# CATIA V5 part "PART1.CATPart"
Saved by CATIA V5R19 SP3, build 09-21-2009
Part number: PART1
Bounding box of the stored display mesh (mm): x -10.392 to 10.392, y -6.9 to 85.6, z -9 to 9
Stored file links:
  C:\Documents and Settings\Frielingsdorf\Desktop\PART1.CATPart
  P1.CATPart
  X:\CATIA\R19\intel_a\reffiles\standard\MetricThickPitch.txt
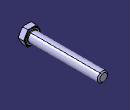
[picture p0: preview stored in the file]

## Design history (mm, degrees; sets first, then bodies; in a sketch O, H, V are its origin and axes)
Body1 "MainBody" (main body), material "Kein"
  Sketch1 on yz-plane, origin (0, 0, 0), H (0, 1, 0), V (0, 0, 1)
    line L1 (0, 8.315) -> (0, 8.9066)
    line L2 (0.6, 8.1967) -> (0.6, 6.6)
    line L3 (1.2, 6) -> (85.6, 6)
    line L4 (85.6, 6) -> (85.6, 0)
    point P3 (85.6, 0)
    line L5 (85.6, 0) -> (0, 0)
    arc A1 centre (0.6, 8.9066) radius 0.6 from (0.5, 8.315) to (0, 8.9066) cw
    arc A2 centre (0.48, 8.1967) radius 0.12 from (0.5, 8.315) to (0.6, 8.1967) cw
    point P8 (0.5, 8.315)
    arc A3 centre (1.2, 6.6) radius 0.6 from (0.6, 6.6) to (1.2, 6) ccw
    line L6 (0, 8.315) -> (0, 0)
    distance L2 L4 = 85
    length L4 = 6
    distance P8 L5 = 8.315
    distance L2 L1 = 0.6
    distance L2 P8 = 0.1
    radius A1 = 0.6
    radius A3 = 0.6
    length L6 = 8.315
    vertical: L1 V, L2 V, L4 V
    horizontal: L3 H, L5 H
    coincidence: P3 H, L6 V
    tangency: A1 L1, A2 L2, A2 A1, A3 L2, A3 L3, L6 A1
  Shaft1: profile Sketch1, axis Y axis, angle 360
  Sketch2 on face of Shaft1 from Sketch1.L6, origin (0, 0, 0), H (1, 0, 0), V (0, 0, 1)
    point P1 (5.1962, -9)
    point P2 (10.3923, 0)
    point P3 (5.1962, 9)
    point P4 (-5.1962, 9)
    point P5 (-10.3923, 0)
    point P6 (-5.1962, -9)
    point P7 (7.7942, -4.5)
    line L1 (5.1962, -9) -> (10.3923, 0)
    line L2 (10.3923, 0) -> (5.1962, 9)
    line L3 (5.1962, 9) -> (-5.1962, 9)
    line L4 (-5.1962, 9) -> (-10.3923, 0)
    line L5 (-10.3923, 0) -> (-5.1962, -9)
    line L6 (-5.1962, -9) -> (5.1962, -9)
    construction line L7 (0, 0) -> (7.7942, -4.5)
    construction circle A1 centre (0, 0) radius 10.3923
    construction arc A2 centre (-10.3923, 0) radius 10.3923 from (-5.1962, 9) to (-5.1962, -9) cw
    construction arc A3 centre (10.3923, 0) radius 10.3923 from (5.1962, 9) to (5.1962, -9) ccw
    construction circle A4 centre (0, 0) radius 9
    reference intersected line E1 through (0, 0) direction (-1, 0) from xy-plane
    distance L4 L1 = 18
    coincidence: A1 P1, A1 P2, A1 P3, A1 P4, A1 P5, A1 P6, A2 O, A3 O
    midpoint: P7 L1
    tangency: A4 L2
    parallelism: L3 E1
  Pad1: profile Sketch2, direction (0, -1, 0), length 6.9
  Sketch3 on xy-plane, origin (0, 0, 0), H (1, 0, 0), V (0, 1, 0)
    line L1 (-10.3923, -6.0962) -> (-10.3923, -6.9)
    line L2 (-10.3923, -6.9) -> (-9, -6.9)
    point P3 (-9, -6.9)
    line L3 (-9, -6.9) -> (-10.3923, -6.0962)
    reference projected line E1 (-10.3923, 0) -> (-10.3923, -6.9) from edge [face of Pad1 from Sketch2.L5 | face of Pad1 from Sketch2.L4]
    reference projected line E2 (-5.1962, -6.9) -> (-10.3923, -6.9) from edge [face of Pad1 from Sketch2.L4 | end face of Pad1]
    angle L3 L2 = 30
    distance P3 V = 9
    coincidence: L1 E1, L2 E2
  Groove1: profile Sketch3, axis Y axis, angle 360
  Chamfer1: length 1.5, angle 45, on edge [face of Shaft1 from Sketch1.L3 | face of Shaft1 from Sketch1.L4]
  Thread1: "M12", diameter 12, depth 30, pitch 1.75, on face of Shaft1 from Sketch1.L3, from face of Shaft1 from Sketch1.L4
